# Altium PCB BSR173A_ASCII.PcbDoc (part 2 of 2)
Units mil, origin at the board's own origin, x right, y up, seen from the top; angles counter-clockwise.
Board outline 3000 x 1500 mil, 4 copper layers (Top Layer, Signal Layer 1, Signal Layer 2, Bottom Layer), stack 61.2 mil thick; 64 components, 17 nets, 119 pads, 82 vias.
Unrouted connection lines stored in the file: 2.
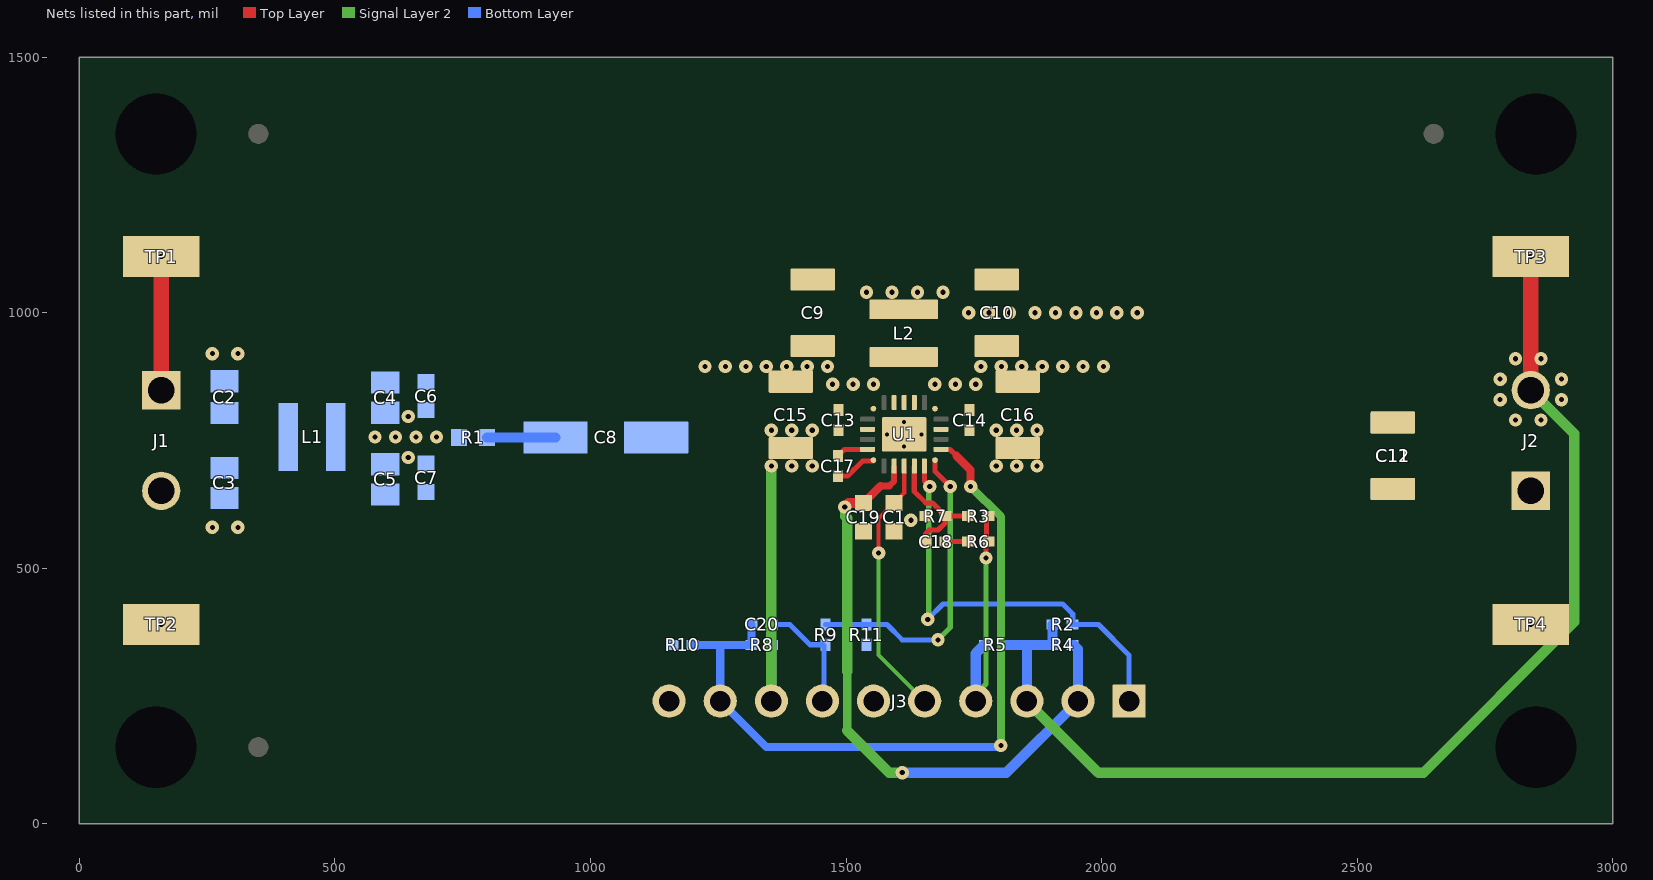
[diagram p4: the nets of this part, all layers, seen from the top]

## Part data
C1 C19: library part CMP-0084111-1, "CAP, CERM, 1 µF, 16 V,+/- 10%, X7R, AEC-Q200 Grade 1, 0603"
C2 C3 C4 C5: library part CMP-0007977-2, "CAP, CERM, 2.2 uF, 50 V, +/- 10%, X7R, AEC-Q200 Grade 1, 0805"
C6 C7: library part CMP-0007097-4, "CAP, CERM, 0.47 uF, 50 V, +/- 10%, X7R, AEC-Q200 Grade 1, 0603"
C8: library part CMP-0092865-1, "68µF 50V Aluminum Electrolytic Capacitors Radial, Can - SMD 680mOhm @ 100kHz 2000 Hrs @ 105°C"
C9 C10 C11 C12: library part CMP-0092443-1, "Multilayer Ceramic Capacitor 47uF 20% 10V 1210 T/R"
C13 C14: library part CMP-0006684-2, "CAP, CERM, 0.022 uF, 50 V, +/- 10%, X7R, 0402"
C15 C16: library part CMP-0092450-1, "10uF @ ±10% 50V Ceramic Capacitor X7R 1210 (3225 Metric)"
C17: library part CMP-0078241-1, "CAP, CERM, 0.1 µF, 10 V,+/- 10%, X7R, 0402"
C18: library part CMP-0006311-2, "CAP, CERM, 22 pF, 50 V, +/- 5%, C0G/NP0, AEC-Q200 Grade 1, 0402"
C20: library part CMP-0006314-2, "CAP, CERM, 1000 pF, 50 V, +/- 10%, X7R, AEC-Q200 Grade 1, 0402"
FID1 FID2 FID3 FID4 FID5 FID6: library part CMP-0077181-1, "Fiducial mark.  There is nothing to buy or mount."
J1 J2: library part CMP-0055486-1, "TERM BLOCK 2POS 5mm, TH"
J3: library part CMP-0075422-1, "Header, 100mil, 10x1, Gold, TH"
L1: library part CMP-0086510-2, "Shielded Power Inductors"
L2: library part CMP-0090843-1, "Power Inductor, shielded, composite, 0.76uH 20% tol, 5.5mOhms, SFR 72MHz, ISAT 5.6A, IRMS14.2ASMT, RoHS, halogen-free"
LBL1: library part CMP-0003625-1, "Thermal Transfer Printable Labels, 0.650\" W x 0.200\" H - 10,000 per roll"
Logo1: library part CMP-0074838-1, "Texas Instrument Corporate Signature"
Logo2: library part CMP-0074769-1
Logo3: library part CMP-0074847-1, "FCC_disclaimer"
LOGO4: library part CMP-0074837-2, "IEC 61010-1 Hot Surface Warning"
Logo5: library part CMP-0074844-1
MH1 MH2 MH3 MH4: library part CMP-0078424-2, "PCB Mounting Hole, No Pad"
R1: library part CMP-0025697-4, "RES, 0, 5%, 0.1 W, AEC-Q200 Grade 0, 0603"
R2 R3 R10 R11: library part CMP-0025950-3, "RES, 100 k, 1%, 0.063 W, AEC-Q200 Grade 0, 0402"
R4: library part CMP-0026129-2, "RES, 1.00, 1%, 0.063 W, AEC-Q200 Grade 0, 0402"
R5: library part CMP-0026404-2, "RES, 49.9, 1%, 0.063 W, AEC-Q200 Grade 0, 0402"
R6: library part CMP-0026071-3, "RES, 1.00 k, 1%, 0.063 W, AEC-Q200 Grade 0, 0402"
R7: library part CMP-0026196-2, "RES, 24.9 k, 1%, 0.063 W, AEC-Q200 Grade 0, 0402"
R8: library part CMP-0026199-2, "RES, 255 k, 1%, 0.063 W, AEC-Q200 Grade 0, 0402"
R9: library part CMP-0026822-3, "RES, 0, 5%, 0.063 W, AEC-Q200 Grade 0, 0402"
SH-J1: library part CMP-0003623-3, "Shunt, 100mil, Gold plated, Black"
TP1 TP2 TP3 TP4: library part CMP-0055162-1, "Test Point, Miniature, SMT"
U1: library part CMP-0092919-2, "Automotive 3-V to 36-V, 6-A Synchronous Buck DC/DC Converter, Adjustable 1-34.2V, VQFN-FCRLF22"
ZZ1: library part CMP-0003616-3
ZZ2: library part CMP-0077236-1
ZZ3: library part CMP-0077237-1
ZZ4 ZZ5 ZZ6: library part CMP-0077238-1

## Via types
v1: diameter 26, hole 10, Top Layer to Bottom Layer, tented both sides, 74 vias
v2: diameter 19.68, hole 7.87, Top Layer to Bottom Layer, 4 vias
v3: diameter 26, hole 10, Top Layer to Bottom Layer, tented bottom, 4 vias

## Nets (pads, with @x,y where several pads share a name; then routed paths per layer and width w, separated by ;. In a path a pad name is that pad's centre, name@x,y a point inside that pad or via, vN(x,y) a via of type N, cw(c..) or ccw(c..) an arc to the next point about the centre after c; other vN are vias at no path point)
BIAS: C19.2 J3.2 R4.2 U1.3 | length 1245.5
  Top Layer w12: 1584.94,661 1594.25,670.32 U1.3@1594.25,697.99
  Top Layer w14: 1567.38,661 1584.94,661
  Top Layer w16: C19.2@1533.94,627.56 1567.38,661
  Top Layer w20: v1(1497.56,620) 1505.12,627.56 C19.2@1533.94,627.56
  Signal Layer 2 w16: 1502.29,182.29 1502.29,297.71
  Signal Layer 2 w20: v1@1497.56,618.38 v1(1497.56,620) 1498.71,618.85 1498.71,601.29 1502.29,597.71 1502.29,297.71 ; 1502.29,182.29 1584.58,100 v1(1610,100)
  Bottom Layer w20: v1(1610,100) 1813.94,100 J3.2@1953.94,240 1953.94,341.34 1945.28,350 R4.2@1943.62,350
EN: C20.2 J3.9 R8.1 R10.1 U1.8 | length 1487
  Top Layer w10: U1.8@1685.79,732.6 1703.7,732.6 1716.3,720
  Top Layer w16: 1716.3,720 1743.94,692.36 v1(1743.94,660)
  Signal Layer 2 w16: v1(1743.94,660) 1803.01,600.93 1803.01,160.08 1801.91,158.98 1801.91,154.11 v1(1803.01,153.01)
  Bottom Layer w16: R10.1@1199.68,350 1255,350 ; R8.1@1310.32,350 1255,350 ; R8.1@1315.32,350 C20.2@1315.31,390 ; v1@1803.01,150 1343.94,150 J3.9@1253.94,240 1253.94,348.94 1255,350
FB: C18.1 R3.1 R7.1 U1.5 | length 249.9
  Top Layer w10: U1.5@1633.62,697.99 1633.62,650.32 1655.94,628 1669.02,628 1679.84,617.18 1679.84,616.69 R7.1@1694.53,602 ; C18.1@1655.47,552 1655.47,567.32 1662.87,574.72 1680.16,574.72 1694.53,589.09 R7.1@1694.53,602 ; R3.1@1739.25,602 R7.1@1694.53,602
GND: C1.2 C2.2 C3.2 C4.2 C5.2 C6.2 C7.2 C8.1 C9.2 C10.2 C11.2 C12.2 C13.2 C14.2 C15.2 C16.2 C19.1 J1.2 J2.1 J3.6 J3.10 R7.2 R10.2 R11.2 TP2.1 TP4.1 U1.12 U1.18 U1.23
  other v1: 260,580 310,580 1626.94,594 1473.94,860 1513.94,860 1553.94,860 1673.94,860 1713.94,860 1753.94,860 1223.94,895 1263.94,895 1303.94,895 1343.94,895 1383.94,895 1423.94,895 1463.94,895 1763.94,895 1803.94,895 1843.94,895 1883.94,895 1923.94,895 1963.94,895 2003.94,895 260,920 310,920
  other v2: 1613.94,738.5 1580.47,762.13 1647.4,762.13 1613.94,785.75
  other v3: 160,390 2840,390
INJ: J3.4 R3.2 R5.2 R6.1 | length 498.1
  Top Layer w10: v1(1773.94,520) R6.1@1773.94,547.91 ; R3.2@1774.84,602 R6.1@1774.84,552 ; R6.1@1778.94,547.91 R6.1@1776.73,550.11 ; R6.1@1780.16,546.69 R6.1@1776.73,550.11 ; R6.1@1774.84,552 R6.1@1776.73,550.11 ; R6.1@1774.84,552 R6.1@1776.73,550.11
  Signal Layer 2 w10: J3.4@1753.94,240 1753.94,253.34 1773.94,273.34 v1(1773.94,520)
  Bottom Layer w20: J3.4@1753.94,240 1753.94,333.34 1770.6,350 R5.2@1772.25,350
NetC8_2: C8.2 R1.1 | length 134
  Bottom Layer w20: R1.1@797.56,756 C8.2@931.57,756
NetC17_1: C17.1 U1.22 | length 64.7
  Top Layer w10: C17.1@1483.94,719.69 1483.94,721.65 1488.78,726.5 1490.75,726.5 1496.85,732.6 U1.22@1542.09,732.6
NetC17_2: C17.2 U1.1 | length 81.9
  Top Layer w10: C17.2@1483.94,680.31 1502.76,680.31 1532.06,709.62 U1.1@1553.71,709.62
NetC18_2: C18.2 R6.2 | length 44.4
  Top Layer w10: C18.2@1694.84,552 R6.2@1739.25,552
NetR9_1: R9.1 R11.1 U1.7 | length 605.4
  Top Layer w10: U1.7@1674.16,709.62 1674.16,689.78 v1(1703.94,660) ; v1@1679.68,360.32 v1(1680,360)
  Signal Layer 2 w10: v1(1680,360) 1703.94,383.94 v1(1703.94,660)
  Bottom Layer w10: R9.1@1459.84,389.84 R9.1@1460,389.68 R11.1@1540,389.68 ; R11.1@1539.84,389.84 1540,390 1580,390 1610,360 v1(1680,360) v1@1679.84,360.16
PGOOD: J3.1 R2.1 U1.6 | length 853.7
  Top Layer w10: U1.6@1653.31,697.99 1653.31,670.63 v1(1663.94,660)
  Signal Layer 2 w10: v1(1660,400) 1661.97,401.97 1661.97,658.03 v1(1663.94,660)
  Bottom Layer w10: v1(1660,400) 1690,430 1923.94,430 1943.62,410.32 R2.1@1943.62,390 1993.94,390 2053.94,330 J3.1@2053.94,240
SW: L2.1 U1.14 U1.15 U1.16
SYNC: C20.1 J3.7 R9.2 | length 229.2
  Bottom Layer w10: C20.1@1354.68,390 1390,390 1429.69,350.31 1455.16,350.31 1456.97,348.5 1456.97,243.03 J3.7@1453.94,240
VCC: C1.1 J3.5 U1.4 | length 516
  Top Layer w8: v1(1563.94,530) 1563.94,597.56 C1.1@1593.94,627.56 1613.94,647.56 U1.4@1613.94,697.99
  Signal Layer 2 w8: v1(1563.94,530) 1563.94,330 J3.5@1653.94,240
VIN: C4.1 C5.1 C6.1 C7.1 C13.1 C14.1 C15.1 C16.1 J3.8 L1.2 R1.2 R8.2 U1.10 U1.20 | length 567.4
  Signal Layer 2 w20: J3.8@1353.94,240 v1(1353.94,700)
  Bottom Layer w20: J3.8@1353.94,240 R8.2@1353.94,347.4
  other v1: 1393.94,700 1433.94,700 1793.94,700 1833.94,700 1873.94,700 643.5,716.9 578.5,756.9 618.5,756.9 658.5,756.9 698.5,756.9 1353.94,770 1393.94,770 1433.94,770 1793.94,770 1833.94,770 1873.94,770 643.5,796.9
VIN_EMI: C2.1 C3.1 J1.1 L1.1 TP1.1 | length 261.6
  Top Layer w30: J1.1@160,848.43 v3(160,1110)
VOUT: C9.1 C10.1 C11.1 C12.1 J2.2 J3.3 L2.2 R2.2 R4.1 R5.1 TP3.1 | length 2244.1
  Top Layer w30: J2.2@2840,848.43 v3(2840,1110)
  Signal Layer 2 w20: J3.3@1853.94,240 1993.94,100 2630,100 2925,395 2925,763.43 J2.2@2840,848.43
  Bottom Layer w20: R5.1@1811.62,350 1853.94,350 ; J3.3@1853.94,240 1853.94,350 ; R2.2@1904.25,390 R4.1@1904.25,350 1853.94,350
  other v1: 2810,790 2860,790 2780,830 2900,830 2780,870 2900,870 2810,910 2860,910 1740,1000 1780,1000 1820,1000 1870,1000 1910,1000 1950,1000 1990,1000 2030,1000 2070,1000 1540,1040 1590,1040 1640,1040 1690,1040
pads on no net: FID1.1 FID2.1 FID3.1 FID4.1 FID5.1 FID6.1 LBL1.0 MH1.1 MH2.1 MH3.1 MH4.1 SH-J1.0 U1.2 U1.9 U1.11 U1.13 U1.17 U1.19 U1.21

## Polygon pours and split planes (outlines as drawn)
SW on Top Layer "TOP_LAYER_SW_P907" (solid, remove dead copper, pour order 907): 1584.02,805 1643.94,805 1643.94,930 1583.86,930
VIN on Top Layer "TOP_LAYER_VIN_P908" (solid, remove dead copper, pour order 908): 1322.7,790 1505.18,790 1516.8,780 1560.15,780 1560.15,760 1516.8,760 1438.43,680 1322.7,680
VIN on Top Layer "TOP_LAYER_VIN_P909" (solid, remove dead copper, pour order 909): 1780.6,680 1907.27,680 1907.27,790 1733.52,790 1725.88,780 1670.6,780 1670.6,760 1710.6,760
VOUT on Top Layer "TOP_LAYER_VOUT_P910" (solid, remove dead copper, pour order 910): 3000,720 3000,1170 1370,1170 1370,980 2510,980 2510,720
GND on Top Layer "TOP-GND-ALL" (solid, remove dead copper, pour order 911): 0,1500 0,0 3000,0 3000,1500
VIN on Signal Layer 2 "SIGNAL_LAYER_2_VIN_P914" (solid, remove dead copper, pour order 914): 1910,680 539.38,680 539.38,830 1910,830
VOUT on Signal Layer 2 "SIGNAL_LAYER_2_VOUT_P915" (solid, remove dead copper, pour order 915): 3000,731.35 3000,1171.35 1370,1171.35 1370,980 2520,980 2520,731.35
GND on Signal Layer 2 "layer3_gnd" (solid, remove dead copper, pour order 916): 0,1500 0,0 3000,0 3000,1500
VIN on Bottom Layer "BOTTOM_LAYER_VIN_P917" (solid, remove dead copper, pour order 917): 468.5,676.9 468.5,837.35 475.82,830.04 770,830.04 770,676.9
VIN_EMI on Bottom Layer "BOTTOM_LAYER_VIN_EMI_P919" (solid, remove dead copper, pour order 919): 12.5,840 12.5,900 230,900 230,830 467.5,830 467.5,670 240,670 240,700 12.5,700
GND on Bottom Layer "BTM-GND-ALL" (solid, remove dead copper, pour order 920): 0,1500 3000,1500 3000,0 0,0
VOUT on Bottom Layer "BOTTOM_LAYER_VOUT_P918" (solid, pour order 918): 2511.04,931.67 2927.66,931.67 2927.66,762.34 2930,760 2509.57,760
GND on Signal Layer 1 "TOP-GND-ALL" (solid, remove dead copper, pour order 913): 0,1500 0,0 3000,0 3000,1500
VOUT on Signal Layer 1 "SIGNAL_LAYER_1_VOUT_P912" (solid, pour order 912): 2751.17,947.25 2927.66,947.25 2927.66,762.34 2930,760 2749.57,760

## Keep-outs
Keep-Out Layer:
  text ".Layer_Name" at 577,-858.49 h60

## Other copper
Top Layer:
  text ".Layer_Name" at 577,-858.49 h60
Signal Layer 1:
  text ".Layer_Name" at 640,-860 h60
Signal Layer 2:
  text ".Layer_Name" at 640,-860 h60
Bottom Layer:
  text ".Layer_Name" at 577,-858.49 h60

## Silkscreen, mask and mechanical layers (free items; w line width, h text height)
Top Overlay:
  circle w10: c1611.85,857.87 r4.92
  text "BSR173 Rev A" at 650,1180 h40
  text "GND" at 1173.94,60 h40 r90
  text "EN" at 1273.94,60 h40 r90
  text "VIN" at 1373.94,60 h40 r90
  text "GND" at 1573.94,60 h40 r90
  text "VCC" at 1673.94,60 h40 r90
  text "INJ" at 1773.94,60 h40 r90
  text "PGD" at 2073.94,60 h40 r90
  text "SYNC" at 1473.94,30 h40 r90
  text "VOUT" at 1873.94,30 h40 r90
  text "BIAS" at 1973.94,30 h40 r90
  text ".Layer_Name" at 577,-858.49 h60
Bottom Overlay:
  text ".Layer_Name" at 577,-858.49 h60
Top Paste:
  text ".Layer_Name" at 577,-858.49 h60
Bottom Paste:
  text ".Layer_Name" at 577,-858.49 h60
Top Solder:
  text ".Layer_Name" at 577,-858.49 h60
  text ".Layer_Name" at 577,-858.49 h60
Bottom Solder:
  text ".Layer_Name" at 577,-858.49 h60
Drill Guide:
  text ".Layer_Name" at 577,-858.49 h60
M1 Board Outline:
  lines w20: 0,0 3000,0 ; 0,0 0,1500 ; 0,0 0,1500 ; 0,0 3000,0 ; 0,0 0,1500 ; 0,0 3000,0 ; 0,0 0,1500 ; 0,0 3000,0 ; 0,0 0,1500 ; 0,0 3000,0 ; 0,1500 3000,1500 ; 0,1500 3000,1500 ; 0,1500 3000,1500 ; 0,1500 3000,1500 ; 0,1500 3000,1500 ; 3000,0 3000,1500 ; 3000,0 3000,1500 ; 3000,0 3000,1500 ; 3000,0 3000,1500 ; 3000,0 3000,1500
  text ".Layer_Name" at 577,-858.49 h60
M2 Board Dimensions:
  rectangle: 0,-275 125,-150
  rectangle: 125,-400 500,-275
  lines w7: 0,-275 1000,-275 ; 0,-150 0,-400 1000,-400 1000,-150 ; 125,-400 125,-150 ; 250,-400 250,-150 ; 500,-400 500,-150 ; 700,-260 1700,-260 ; 750,-400 750,-150
  text ".Layer_Name" at 577,-858.49 h60
M3 3D STEP Top:
  text ".Layer_Name" at 577,-858.49 h60
M4 3D STEP Bottom:
  text ".Layer_Name" at 577,-858.49 h60
M5 Assembly Top:
  lines w10: -292,-930.17 6308,-930.17 ; -292,-726.83 6310,-726.83 ; -292,-523.5 -292,-1133.5 3713,-1133.5 6310,-1133.5 6310,-523.5 -291.5,-523.5 -291.5,-1133.5 1284,-1133.5 ; 2173,-1133.5 2173,-523.5 ; 3440,-726.83 3440,-523.5 ; 4280,-726.83 4280,-523.5 ; 4902,-1140 4902,-937.17
  text "COMPONENTS MARKED 'DNP' SHOULD NOT BE POPULATED." at 1153.5,-318.5 h60
  text "ASSEMBLY VARIANT:" at 1153,-434 h60
  text ".VariantName" at 2189,-434 h60
  text "PCB VIEWED FROM TOP SIDE" at -228.5,-655.67 h60
  text "BOARD #:" at 2248,-655.67 h60
  text ".PRJ_Number" at 2793.5,-655.67 h60
  text "REV:" at 3638,-655.67 h60
  text ".PCB_Rev" at 3929.5,-655.67 h60
  text "SVN REV:" at 4476,-655.67 h60
  text ".VersionControl_RevNumber" at 4982,-655.67 h60
  text "TID #:" at 2248,-859 h60
  text ".TID" at 2793.5,-859 h60
  text "PLOT NAME =" at -228.5,-1064.34 h60
  text ".plot_File_Name" at 577,-1064.34 h60
  text "GENERATED    :" at 2250,-1064.34 h60
  text ".Print_Date" at 3119.5,-1064.34 h60
  text ".Print_Time" at 3848.5,-1064.34 h60
  text "TEXAS INSTRUMENTS" at 5113,-1064.34 h60
M6 Assembly Bottom:
  lines w10: -292.5,-727.33 6309.5,-727.33 ; -290.5,-930.67 6309.5,-930.67 ; 1115.5,-1140.5 1115.5,-937.67 ; 1737.5,-727.33 1737.5,-524 ; 2577.5,-727.33 2577.5,-524 ; 3844.5,-1134 3844.5,-524 ; 4733.5,-1134 6309,-1134 6309,-524 -292.5,-524 -292.5,-1134 2304.5,-1134 6309.5,-1134 6309.5,-524
  text "COMPONENTS MARKED 'DNP' SHOULD NOT BE POPULATED." at 6102,-318 h60
  text ".VariantName" at 5058,-434 h60
  text "ASSEMBLY VARIANT:" at 6097,-434 h60
  text ".VersionControl_RevNumber" at 1035.5,-656.17 h60
  text "SVN REV:" at 1541.5,-656.17 h60
  text ".PCB_Rev" at 2088,-656.17 h60
  text "REV:" at 2379.5,-656.17 h60
  text ".PRJ_Number" at 3224,-656.17 h60
  text "BOARD #:" at 3769.5,-656.17 h60
  text "PCB VIEWED FROM BOTTOM SIDE" at 6246,-656.17 h60
  text ".TID" at 3224,-859.5 h60
  text "TID #:" at 3769.5,-859.5 h60
  text "TEXAS INSTRUMENTS" at 904.5,-1064.84 h60
  text ".Print_Time" at 2169,-1064.84 h60
  text ".Print_Date" at 2898,-1064.84 h60
  text "GENERATED    :" at 3767.5,-1064.84 h60
  text ".plot_File_Name" at 5440.5,-1064.84 h60
  text "PLOT NAME =" at 6246,-1064.84 h60
M9 Title Sheet:
  lines w10: -491.5,1041.5 -291.5,1041.5 ; -491.5,3416.5 -291.5,3416.5 ; -491.5,5791.5 -291.5,5791.5 ; 2008.5,-1333.5 2008.5,-1133.5 ; 2008.5,7966.5 2008.5,8166.5 ; 4508.5,-1333.5 4508.5,-1133.5 ; 4508.5,7966.5 4508.5,8166.5 ; 6321,-1133.5 6321,-523.5 11303.5,-523.5 ; 7008.5,-1333.5 7008.5,-1133.5 ; 7008.5,7966.5 7008.5,8166.5 ; 9508.5,-1333.5 9508.5,-1133.5 ; 9508.5,7966.5 9508.5,8166.5 ; 11303.5,-1133.5 11303.5,-523.5 ; 11303.5,-823.5 14303.5,-823.5 ; 11303.5,-223.5 14303.5,-223.5 ; 11304.5,370.5 14304.5,370.5 ; 12008.5,-1333.5 12008.5,-1133.5 ; 12008.5,7966.5 12008.5,8166.5 ; 12808.5,-1123.5 12808.5,-523.5 ; 14303.5,-523.5 11303.5,-523.5 ; 14303.5,76.5 11303.5,76.5 ; 14308.5,66.5 14308.5,-1133.5 ; 14308.5,871 11304.5,871 11303.5,871 11303.5,370.5 11303.5,76.5 ; 14308.5,1041.5 14508.5,1041.5 ; 14308.5,3416.5 14508.5,3416.5 ; 14308.5,5791.5 14508.5,5791.5 ; 11303.5,-523.5 11303.5,76.5 ; 14308.5,-1133.5 14308.5,7966.5 -291.5,7966.5 -291.5,-1133.5 14308.5,-1133.5 ; -491.5,-1333.5 -491.5,8166.5 14508.5,8166.5 14508.5,-1333.5 -491.5,-1333.5
  text "1" at 739.84,8036.5 h70
  text "2" at 3235.5,8036.5 h70
  text "3" at 5724.84,8036.5 h70
  text "4" at 8231.51,8036.5 h70
  text "5" at 10730.5,8036.5 h70
  text "6" at 13235.5,8036.5 h70
  text "A" at -416.5,6893.5 h70
  text "A" at 14383.5,6893.5 h70
  text "B" at -416.5,4513.5 h70
  text "B" at 14383.5,4513.5 h70
  text "C" at -416.5,2138.5 h70
  text "C" at 14383.5,2138.5 h70
  text "PROJECT TITLE:" at 11343.5,277.5 h45
  text ".PRJ_Title" at 11393.5,144.17 h70
  text "DESIGNED FOR:" at 11343.5,-23.5 h45
  text ".PRJ_Customer" at 11393.5,-163.5 h70
  text "D" at -416.5,-231.5 h70
  text "D" at 14383.5,-231.5 h70
  text "FILE NAME:" at 11343.5,-323.5 h45
  text ".PCB_File_Name_No_Path" at 11393.5,-443.5 h70
  text "Texas Instruments (TI) and/or its licensors do not warrant the accuracy or completeness of this specification" at 6374,-605.34 h45
  text "ENGINEER:" at 11343.5,-613.5 h45
  text "LAYOUT BY:" at 12848.5,-613.5 h45
  text "or any information contained therein. TI and/or its licensors do not warrant that this design will meet" at 6329.01,-718 h45
  text ".PRJ_Engineer" at 11393.5,-768.49 h70
  text ".PCB_Layout" at 12899,-768.49 h70
  text "the specifications, will be suitable for your application or fit for any particular purpose, or will operate in" at 6329.01,-830.67 h45
  text ".Layer_Name" at 577,-858.49 h60
  text "ALTIUM DESIGNER VERSION:" at 12848.5,-923.5 h45
  text "an implementation. TI and/or its licensors do not warrant that the design is production worthy. You should" at 6329.01,-943.33 h45
  text "completely validate and test your design implementation to confirm the system functionality for your application." at 6374,-1056 h45
  text ".print_Scale" at 11393.5,-1056.83 h70
  text ".Application_BuildNumber" at 12899,-1056.83 h70
  text "1" at 739.84,-1263.5 h70
  text "2" at 3235.5,-1263.5 h70
  text "3" at 5724.84,-1263.5 h70
  text "4" at 8231.51,-1263.5 h70
  text "5" at 10730.5,-1263.5 h70
  text "6" at 13235.5,-1263.5 h70
M10 Fab Notes:
  drawing of 189 lines, arcs and shapes, not listed
  text "DESIGN INFORMATION" at 12382.02,6356.17 h60
  text "MIN. TRACK WIDTH:" at 11737.46,6224.05 h60
  text "8" at 12833.7,6224.05 h60
  text "MIL" at 12988.46,6224.05 h60
  text "MIN. CLEARANCE:" at 11737.46,6099.92 h60
  text "0.2" at 12773.7,6099.93 h60
  text "mm" at 12988.46,6099.92 h60
  text "MIN. VIA PAD SIZE:" at 11737.46,5975.8 h60
  text "MIL" at 13150,5970 h60
  text "19.685" at 12660,5960 h60
  text "0.05mm (2MIL)" at 12432.46,5845.9 h60
  text "MINIMUM ANNULAR RING" at 11408.23,5837.67 h60
  text "EXTERNAL" at 13140.46,5837.67 h60
  text "PER" at 11608.23,5727.55 h60
  text "IPC-D-275 CLASS 2 LEVEL C" at 11828.23,5727.54 h60
  text "MIL, HOLES" at 13316.46,5627.07 h60
  text "+/-" at 12924,5618.48 h60
  text "+/-" at 13778,5618.48 h60
  text "REGISTRATION TOLERANCES:" at 11408.23,5617.42 h60
  text "METAL" at 12608,5617.42 h60
  text "5" at 13184.2,5617.42 h60
  text "3" at 14017.2,5617.42 h60
  text "MIL" at 14133.46,5617.42 h60
  text "HOLE SIZE TOLERANCE (UNLESS OTHERWISE SPECIFIED):" at 11408.23,5519.1 h60
  text "+/-" at 13778,5516.23 h60
  text "3" at 14017.2,5515.17 h60
  text "MIL" at 14133.46,5515.17 h60
  text "MATERIAL:" at 11333.46,5377.52 h60
  text "FR-4 High Tg" at 12319.9,5249 h60
  text "X" at 12175.46,5241.01 h60
  text "FR-408" at 11754.46,5236.49 h60
  text "OTHER" at 13242.46,5236.49 h60
  text "65 MIL (1.6mm) +/-10%" at 12074.56,5093.46 h60
  text "X" at 11954.46,5091.01 h60
  text "THICKNESS:" at 11408.23,5085.24 h60
  text "OTHER" at 13359.46,5085.24 h60
  text "TOLERANCE:" at 11408.23,4946.92 h60
  text "X" at 12256.46,4946.92 h60
  text "ANSI IPC-6012 TYPE 3 CLASS 2" at 12434.48,4946.92 h60
  text "OTHER +/-" at 12434.46,4802.73 h60
  text "BOW & TWIST:" at 11408.23,4657.54 h60
  text "X" at 12256.46,4657.54 h60
  text "ANSI IPC-6012 TYPE 3 CLASS 2" at 12434.48,4657.54 h60
  text "OTHER +/-" at 12434.46,4510.85 h60
  text "DRILLING:" at 11333.46,4380.23 h60
  text "NC_DRILL FILES" at 13094.46,4275.04 h60
  text "REFERENCE:" at 11408.23,4271.1 h60
  text "X" at 12065.46,4271.01 h60
  text "AS SHOWN" at 12243.46,4271.1 h60
  text "X" at 12966.46,4271.1 h60
  text "OTHER" at 13392.46,4128.85 h60
  text "PTH COPPER THICKNESS:" at 11407.91,4125.32 h60
  text "X" at 12547.14,4125.32 h60
  text "20-30 um" at 12675.14,4125.32 h60
  text "BOARD FINISH:" at 11333.46,3977.73 h60
  text "SILKSCREEN:" at 11488.68,3867.6 h60
  text "X" at 12446.46,3867.6 h60
  text "TOP" at 12563.46,3867.6 h60
  text "X" at 12956.46,3867.6 h60
  text "BOTTOM" at 13074.46,3867.6 h60
  text "SILKSCREEN COLOR:" at 11488.68,3712.41 h60
  text "X" at 12445.46,3712.41 h60
  text "WHITE" at 12563.46,3712.41 h60
  text "OTHER" at 13074.46,3712.41 h60
  text "X" at 12576.46,3568.96 h60
  text "GREEN" at 12694.46,3568.96 h60
  text "OTHER" at 13312.46,3568.96 h60
  text "SOLDER RESIST COLOR:" at 11488.68,3562.1 h60
  text "X" at 12576.46,3414.71 h60
  text "MATTE" at 12694.46,3414.71 h60
  text "SEMI-GLOSS" at 13312,3414.07 h60
  text "IMMERSION GOLD (ENIG)" at 12394.46,3241.94 h60
  text "ENEPIG" at 13732,3234.72 h60
  text "SURFACE FINISH:" at 11333.46,3233.72 h60
  text "X" at 12216.46,3233.72 h60
  text "IMM. TIN/SILVER OR EQUIV" at 11663,3096.4 h60
  text "OTHER" at 13094.46,3092.47 h60
  text "ARRAY/PANEL:" at 11333.46,2937.09 h60
  text "CUT AND TRIM PER M1 BOARD OUTLINE" at 12394.46,2928.87 h60
  text "N.C. ROUTE" at 12394.46,2792.9 h60
  text "X" at 13082.46,2792.9 h60
  text "V. SCORE" at 13260.46,2792.9 h60
  text "CERTIFICATION:" at 11333.46,2663.77 h60
  text "MATERIALS AND WORKMANSHIP FOR ALL PCBS" at 12058.46,2663.77 h60
  text "TO MEET OR EXCEED THE REQUIREMENTS OF:" at 12058.46,2569.71 h60
  text "X" at 11695.97,2441.08 h60
  text "ANSI IPC-A-600F CLASS ->" at 11823.96,2441.08 h60
  text "X" at 13471.97,2441.08 h60
  text "2" at 13581.96,2441.08 h60
  text "1" at 13266.96,2439.58 h60
  text "3" at 13935.96,2439.58 h60
  text "X" at 12507.97,2293.39 h60
  text "RoHS" at 12635.96,2293.39 h60
  text "OTHER" at 13280.36,2293.39 h60
  text "PER ORDER" at 13677.42,2293.39 h60
  text "ALL BOARDS MUST MEET OR EXCEED UL94-V0 REQUIREMENTS." at 11361,2139.57 h60
  text "PCB MUST BEAR THE UL94V-0 UL REGISTERED MATERIAL ID NUMBER" at 11361,2023.5 h60
  text "ADDITIONAL REQUIREMENTS:" at 11333.46,1854.08 h60
  text "MICROSECTION:" at 11408.23,1746.95 h60
  text "YES" at 12313.96,1746.95 h60
  text "REQUIRED" at 13175.46,1602.62 h60
  text "BARE BOARD ELEC. TEST:" at 11408.23,1599.76 h60
  text "NONE" at 12713.96,1599.76 h60
  text "X" at 13057.46,1599.76 h60
  text "PER ORDER" at 13767.46,1599.76 h60
  text "XX MIL VIAS REQUIRE NON-CONDUCTIVE FILL AND PLANARIZE" at 11576.38,1394.82 h59
  text "XX MIL VIAS REQUIRE CONDUCTIVE FILL AND PLANARIZE" at 11584.38,1290.84 h60
  text "OUTER XX MIL TRACES REQUIRE 50 OHM SINGLE-ENDED IMPEDANCE" at 11583.39,1127.46 h58
  text "LAYER 2 & 3 (INNER LAYERS) XX MIL WIDE, XX MIL SPACE / TRACES REQUIRE 100 OHM DIFFERENTIAL IMPEDANCE" at 11575.39,891.74 h60
  text ".Layer_Name" at 577,-858.49 h60
M11 Gerber Information:
  lines w10: -292,-930.17 6308,-930.17 ; -292,-726.83 6310,-726.83 ; -292,-523.5 -292,-1133.5 3713,-1133.5 6310,-1133.5 6310,-523.5 -291.5,-523.5 -291.5,-1133.5 1284,-1133.5 ; 2173,-1133.5 2173,-523.5 ; 3440,-726.83 3440,-523.5 ; 4280,-726.83 4280,-523.5 ; 4902,-1140 4902,-937.17
  text "ALL ARTWORK VIEWED FROM TOP SIDE" at -228.5,-655.67 h60
  text "BOARD #:" at 2248,-655.67 h60
  text ".PRJ_Number" at 2793.5,-655.67 h60
  text "REV:" at 3638,-655.67 h60
  text ".PCB_Rev" at 3929.5,-655.67 h60
  text "SVN REV:" at 4476,-655.67 h60
  text ".VersionControl_RevNumber" at 4982,-655.67 h60
  text "LAYER NAME =" at -228.5,-858.49 h60
  text "TID #:" at 2248,-859 h60
  text ".TID" at 2793.5,-859 h60
  text "PLOT NAME =" at -228.5,-1064.34 h60
  text ".plot_File_Name" at 577,-1064.34 h60
  text "GENERATED    :" at 2250,-1064.34 h60
  text ".Print_Date" at 3119.5,-1064.34 h60
  text ".Print_Time" at 3848.5,-1064.34 h60
  text "TEXAS INSTRUMENTS" at 5113,-1064.34 h60
M12 Stackup:
  drawing of 295 lines, arcs and shapes, not listed
  text "Layer" at 6695.46,7760.01 h60
  text "Name" at 7105.37,7760.01 h60
  text "Material" at 8045.11,7760.01 h60
  text "Thickness" at 8904.88,7760.01 h60
  text "Constant" at 9554.71,7760.01 h60
  text "Board Layer Stack" at 10124.57,7760.01 h60
  text "Top Overlay" at 7105.37,7640.01 h60
  text "Top Solder" at 7105.37,7520.01 h60
  text "Solder Resist" at 8045.11,7520.01 h60
  text "0.40mil" at 8904.88,7520.01 h60
  text "3.5" at 9554.71,7520.01 h60
  text "1" at 6695.46,7400.01 h60
  text "Top Layer" at 7105.37,7400.01 h60
  text "2.80mil" at 8904.88,7400.01 h60
  text "Dielectric 1" at 7105.37,7280.01 h60
  text "FR-4 High Tg" at 8045.11,7280.01 h60
  text "5.00mil" at 8904.88,7280.01 h60
  text "4.2" at 9554.71,7280.01 h60
  text "2" at 6695.46,7160.01 h60
  text "Signal Layer 1" at 7105.37,7160.01 h60
  text "2.80mil" at 8904.88,7160.01 h60
  text "Dielectric 2" at 7105.37,7040.01 h60
  text "FR-4 High Tg" at 8045.11,7040.01 h60
  text "40.00mil" at 8904.88,7040.01 h60
  text "4.2" at 9554.71,7040.01 h60
  text "3" at 6695.46,6920.01 h60
  text "Signal Layer 2" at 7105.37,6920.01 h60
  text "2.80mil" at 8904.88,6920.01 h60
  text "Dielectric 3" at 7105.37,6800.01 h60
  text "FR-4 High Tg" at 8045.11,6800.01 h60
  text "5.00mil" at 8904.88,6800.01 h60
  text "4.2" at 9554.71,6800.01 h60
  text "4" at 6695.46,6680.01 h60
  text "Bottom Layer" at 7105.37,6680.01 h60
  text "2.80mil" at 8904.88,6680.01 h60
  text "Bottom Solder" at 7105.37,6560.01 h60
  text "Solder Resist" at 8045.11,6560.01 h60
  text "0.40mil" at 8904.88,6560.01 h60
  text "3.5" at 9554.71,6560.01 h60
  text "Bottom Overlay" at 7105.37,6440.01 h60
  text "Total board thickness:" at 6695.46,6320.01 h60
  text "62.00mil" at 8904.88,6320.01 h60
  text ".Layer_Name" at 577,-858.49 h60
M13 Component Bodies Top:
  text ".Layer_Name" at 577,-858.49 h60
M14 Component Bodies Bottom:
  text ".Layer_Name" at 577,-858.49 h60
M15 Courtyards Top:
  text ".Layer_Name" at 577,-858.49 h60
M16 Courtyards Bottom:
  text ".Layer_Name" at 577,-858.49 h60
Drill Drawing:
  circle w10: c8014.35,5567.06 r27.63
  lines w10: 7986.72,5290.8 8041.98,5290.8 8041.98,5346.05 7986.72,5346.05 7986.72,5290.8 ; 7986.72,5415.12 8014.35,5428.93 8041.98,5415.12 8028.16,5442.74 8041.98,5470.37 8014.35,5456.56 7986.72,5470.37 8000.54,5442.74 7986.72,5415.12 ; 7986.72,5663.76 7986.72,5677.57 8000.54,5691.38 7986.72,5705.2 7986.72,5719.01 8000.54,5719.01 8014.35,5705.2 8028.16,5719.01 8041.98,5719.01 8041.98,5705.2 8028.16,5691.38 8041.98,5677.57 8041.98,5663.76 8028.16,5663.76 8014.35,5677.57 8000.54,5663.76 7986.72,5663.76 ; 7986.72,5801.89 8000.54,5801.89 8000.54,5788.08 8028.16,5788.08 8028.16,5801.89 8041.98,5801.89 8041.98,5829.52 8028.16,5829.52 8028.16,5843.33 8000.54,5843.33 8000.54,5829.52 7986.72,5829.52 7986.72,5801.89
  lines w12: 7936.63,5253.5 11168.12,5253.5 ; 7936.63,5875.1 11168.12,5875.1 ; 8274.5,5129.18 8274.5,5999.42 ; 8606.5,5129.18 8606.5,5999.42 ; 9243.06,5129.18 9243.06,5999.42 ; 9502.2,5129.18 9502.2,5999.42 ; 9877.36,5129.18 9877.36,5999.42 ; 10601.69,5129.18 10601.69,5999.42 ; 7936.63,5129.18 11168.12,5129.18 11168.12,5999.42 7936.63,5999.42 7936.63,5129.18
  text "Symbol" at 8011.23,5912.4 h72
  text "Quantity" at 8311.79,5912.4 h72
  text "Finished Hole Size" at 8643.79,5912.4 h72
  text "Plated" at 9280.36,5912.4 h72
  text "Hole Type" at 9539.5,5912.4 h72
  text "Drill Layer Pair" at 9914.65,5912.4 h72
  text "Hole Tolerance" at 10638.98,5912.4 h72
  text "4" at 8311.79,5788.08 h60
  text "159.00mil (4.039mm)" at 8643.79,5788.08 h60
  text "NPTH" at 9280.36,5788.08 h60
  text "Round" at 9539.5,5788.08 h60
  text "Top Layer - Bottom Layer" at 9914.65,5788.08 h60
  text "4" at 8311.79,5663.76 h60
  text "7.87mil (0.200mm)" at 8643.79,5663.76 h60
  text "PTH" at 9280.36,5663.76 h60
  text "Round" at 9539.5,5663.76 h60
  text "Top Layer - Bottom Layer" at 9914.65,5663.76 h60
  text "78" at 8311.79,5539.44 h60
  text "10.00mil (0.254mm)" at 8643.79,5539.44 h60
  text "PTH" at 9280.36,5539.44 h60
  text "Round" at 9539.5,5539.44 h60
  text "Top Layer - Bottom Layer" at 9914.65,5539.44 h60
  text "10" at 8311.79,5415.12 h60
  text "40.00mil (1.016mm)" at 8643.79,5415.12 h60
  text "PTH" at 9280.36,5415.12 h60
  text "Round" at 9539.5,5415.12 h60
  text "Top Layer - Bottom Layer" at 9914.65,5415.12 h60
  text "4" at 8311.79,5290.8 h60
  text "51.18mil (1.300mm)" at 8643.79,5290.8 h60
  text "PTH" at 9280.36,5290.8 h60
  text "Round" at 9539.5,5290.8 h60
  text "Top Layer - Bottom Layer" at 9914.65,5290.8 h60
  text "100 Total" at 8311.79,5166.48 h60
  text ".Layer_Name" at 577,-858.49 h60
Mechanical 17:
  text ".Layer_Name" at 577,-858.49 h60
Mechanical 18:
  text ".Layer_Name" at 577,-858.49 h60
Mechanical 19:
  text ".Layer_Name" at 577,-858.49 h60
